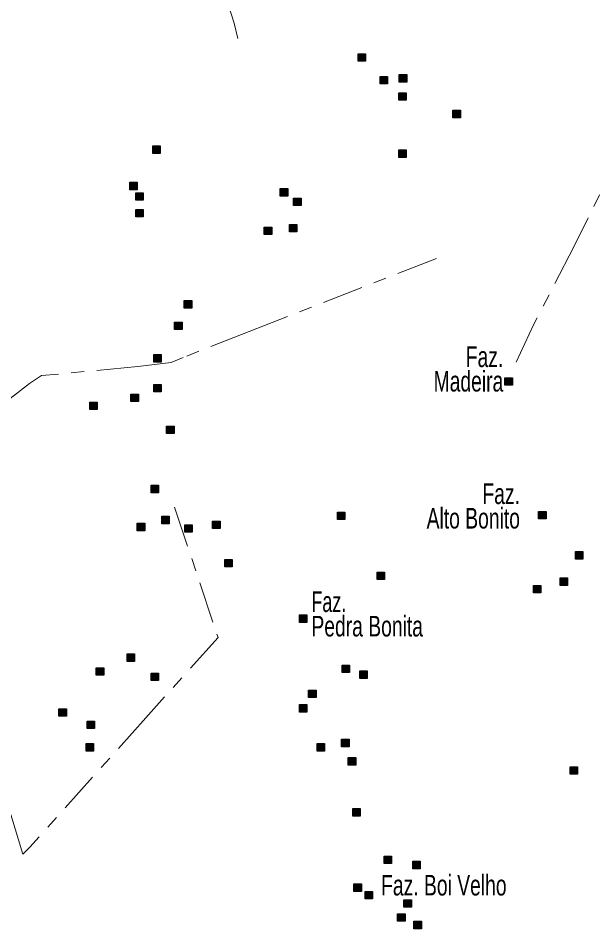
# Model space of a CAD drawing. Extents: x 445.4 to 500, y 8728.7 to 8784.
# Drawn here: x 450 to 454.47, y 8750.73 to 8757.8 of the extents above; entities that cross this region are included whole.
import ezdxf
from ezdxf.enums import TextEntityAlignment as Align

# ---------------------------------------------------------------- set-up
doc = ezdxf.new("R2010")
doc.units = 0
doc.header["$LTSCALE"] = 0.064
doc.linetypes.add('DOT_DASHED', pattern=[7.7, 5, -1.2, 0.3, -1.2])
doc.layers.add('2', color=7, linetype='Continuous', lineweight=25)
doc.layers.add('22', color=7, linetype='DOT_DASHED', lineweight=13)
doc.layers.add('61', color=7, linetype='Continuous')

msp = doc.modelspace()

# ---------------------------------------------------------------- hatches: boundary and pattern name
at = {"layer": '2'}
for points in [[(452.6438, 8757.5206), (452.7018, 8757.5206), (452.7018, 8757.4626), (452.6438, 8757.4626)], [(452.8139, 8757.3441), (452.8719, 8757.3441), (452.8719, 8757.2861), (452.8139, 8757.2861)], [(452.9632, 8757.3577), (453.0212, 8757.3577), (453.0212, 8757.2997), (452.9632, 8757.2997)], [(452.9587, 8757.2173), (453.0167, 8757.2173), (453.0167, 8757.1593), (452.9587, 8757.1593)], [(453.3795, 8757.0815), (453.4375, 8757.0815), (453.4375, 8757.0235), (453.3795, 8757.0235)], [(451.0494, 8756.8038), (451.1074, 8756.8038), (451.1074, 8756.7458), (451.0494, 8756.7458)], [(452.9582, 8756.7736), (453.0162, 8756.7736), (453.0162, 8756.7156), (452.9582, 8756.7156)], [(450.8714, 8756.522), (450.9294, 8756.522), (450.9294, 8756.464), (450.8714, 8756.464)], [(452.0392, 8756.4731), (452.0972, 8756.4731), (452.0972, 8756.4151), (452.0392, 8756.4151)], [(450.9169, 8756.4399), (450.9749, 8756.4399), (450.9749, 8756.3819), (450.9169, 8756.3819)], [(452.1427, 8756.3985), (452.2007, 8756.3985), (452.2007, 8756.3405), (452.1427, 8756.3405)], [(450.9169, 8756.3115), (450.9749, 8756.3115), (450.9749, 8756.2535), (450.9169, 8756.2535)], [(452.1096, 8756.1954), (452.1676, 8756.1954), (452.1676, 8756.1374), (452.1096, 8756.1374)], [(451.915, 8756.1747), (451.973, 8756.1747), (451.973, 8756.1167), (451.915, 8756.1167)], [(451.2938, 8755.6029), (451.3518, 8755.6029), (451.3518, 8755.5449), (451.2938, 8755.5449)], [(451.2192, 8755.4371), (451.2772, 8755.4371), (451.2772, 8755.3791), (451.2192, 8755.3791)], [(451.0577, 8755.1844), (451.1157, 8755.1844), (451.1157, 8755.1264), (451.0577, 8755.1264)], [(453.783, 8755.005), (453.841, 8755.005), (453.841, 8754.947), (453.783, 8754.947)], [(451.0577, 8754.9523), (451.1157, 8754.9523), (451.1157, 8754.8943), (451.0577, 8754.8943)], [(450.8796, 8754.8777), (450.9376, 8754.8777), (450.9376, 8754.8197), (450.8796, 8754.8197)], [(450.5608, 8754.8156), (450.6188, 8754.8156), (450.6188, 8754.7576), (450.5608, 8754.7576)], [(451.1571, 8754.6291), (451.2151, 8754.6291), (451.2151, 8754.5711), (451.1571, 8754.5711)], [(451.037, 8754.1691), (451.095, 8754.1691), (451.095, 8754.1111), (451.037, 8754.1111)], [(451.1198, 8753.9288), (451.1778, 8753.9288), (451.1778, 8753.8708), (451.1198, 8753.8708)], [(452.4823, 8753.9619), (452.5403, 8753.9619), (452.5403, 8753.9039), (452.4823, 8753.9039)], [(454.0446, 8753.9667), (454.1026, 8753.9667), (454.1026, 8753.9087), (454.0446, 8753.9087)], [(450.9293, 8753.8749), (450.9873, 8753.8749), (450.9873, 8753.8169), (450.9293, 8753.8169)], [(451.2979, 8753.8625), (451.3559, 8753.8625), (451.3559, 8753.8045), (451.2979, 8753.8045)], [(451.5133, 8753.8915), (451.5713, 8753.8915), (451.5713, 8753.8335), (451.5133, 8753.8335)], [(454.3297, 8753.6543), (454.3877, 8753.6543), (454.3877, 8753.5963), (454.3297, 8753.5963)], [(451.6085, 8753.594), (451.6665, 8753.594), (451.6665, 8753.536), (451.6085, 8753.536)], [(452.7913, 8753.4958), (452.8493, 8753.4958), (452.8493, 8753.4378), (452.7913, 8753.4378)], [(454.212, 8753.4505), (454.27, 8753.4505), (454.27, 8753.3925), (454.212, 8753.3925)], [(454.0039, 8753.3917), (454.0619, 8753.3917), (454.0619, 8753.3337), (454.0039, 8753.3337)], [(452.1883, 8753.163), (452.2463, 8753.163), (452.2463, 8753.105), (452.1883, 8753.105)], [(450.8506, 8752.8605), (450.9086, 8752.8605), (450.9086, 8752.8025), (450.8506, 8752.8025)], [(450.6104, 8752.7528), (450.6684, 8752.7528), (450.6684, 8752.6948), (450.6104, 8752.6948)], [(452.5196, 8752.7735), (452.5776, 8752.7735), (452.5776, 8752.7155), (452.5196, 8752.7155)], [(452.6563, 8752.7279), (452.7143, 8752.7279), (452.7143, 8752.6699), (452.6563, 8752.6699)], [(451.037, 8752.7113), (451.095, 8752.7113), (451.095, 8752.6533), (451.037, 8752.6533)], [(452.2587, 8752.5787), (452.3167, 8752.5787), (452.3167, 8752.5207), (452.2587, 8752.5207)], [(452.1883, 8752.4668), (452.2463, 8752.4668), (452.2463, 8752.4088), (452.1883, 8752.4088)], [(450.3206, 8752.4337), (450.3786, 8752.4337), (450.3786, 8752.3757), (450.3206, 8752.3757)], [(450.54, 8752.3384), (450.598, 8752.3384), (450.598, 8752.2804), (450.54, 8752.2804)], [(450.5318, 8752.1643), (450.5898, 8752.1643), (450.5898, 8752.1063), (450.5318, 8752.1063)], [(452.325, 8752.1643), (452.383, 8752.1643), (452.383, 8752.1063), (452.325, 8752.1063)], [(452.5155, 8752.1975), (452.5735, 8752.1975), (452.5735, 8752.1395), (452.5155, 8752.1395)], [(452.5671, 8752.055), (452.6251, 8752.055), (452.6251, 8751.997), (452.5671, 8751.997)], [(454.2889, 8751.9837), (454.3469, 8751.9837), (454.3469, 8751.9257), (454.2889, 8751.9257)], [(452.6024, 8751.6588), (452.6604, 8751.6588), (452.6604, 8751.6008), (452.6024, 8751.6008)], [(452.8456, 8751.291), (452.9036, 8751.291), (452.9036, 8751.233), (452.8456, 8751.233)], [(453.0673, 8751.2502), (453.1253, 8751.2502), (453.1253, 8751.1922), (453.0673, 8751.1922)], [(452.6107, 8751.0745), (452.6687, 8751.0745), (452.6687, 8751.0165), (452.6107, 8751.0165)], [(452.6977, 8751.0165), (452.7557, 8751.0165), (452.7557, 8750.9585), (452.6977, 8750.9585)], [(452.9994, 8750.9514), (453.0574, 8750.9514), (453.0574, 8750.8934), (452.9994, 8750.8934)], [(452.9496, 8750.8428), (453.0076, 8750.8428), (453.0076, 8750.7848), (452.9496, 8750.7848)], [(453.0763, 8750.7839), (453.1343, 8750.7839), (453.1343, 8750.7259), (453.0763, 8750.7259)]]:
    msp.add_hatch(color=256, dxfattribs=at).paths.add_polyline_path(points)

# ---------------------------------------------------------------- linework, layer by layer
for points in [[(452.6438, 8757.5206), (452.7018, 8757.5206), (452.7018, 8757.4626), (452.6438, 8757.4626)], [(452.8139, 8757.3441), (452.8719, 8757.3441), (452.8719, 8757.2861), (452.8139, 8757.2861)], [(452.9632, 8757.3577), (453.0212, 8757.3577), (453.0212, 8757.2997), (452.9632, 8757.2997)], [(452.9587, 8757.2173), (453.0167, 8757.2173), (453.0167, 8757.1593), (452.9587, 8757.1593)], [(453.3795, 8757.0815), (453.4375, 8757.0815), (453.4375, 8757.0235), (453.3795, 8757.0235)], [(451.0494, 8756.8038), (451.1074, 8756.8038), (451.1074, 8756.7458), (451.0494, 8756.7458)], [(452.9582, 8756.7736), (453.0162, 8756.7736), (453.0162, 8756.7156), (452.9582, 8756.7156)], [(450.8714, 8756.522), (450.9294, 8756.522), (450.9294, 8756.464), (450.8714, 8756.464)], [(452.0392, 8756.4731), (452.0972, 8756.4731), (452.0972, 8756.4151), (452.0392, 8756.4151)], [(450.9169, 8756.4399), (450.9749, 8756.4399), (450.9749, 8756.3819), (450.9169, 8756.3819)], [(452.1427, 8756.3985), (452.2007, 8756.3985), (452.2007, 8756.3405), (452.1427, 8756.3405)], [(450.9169, 8756.3115), (450.9749, 8756.3115), (450.9749, 8756.2535), (450.9169, 8756.2535)], [(452.1096, 8756.1954), (452.1676, 8756.1954), (452.1676, 8756.1374), (452.1096, 8756.1374)], [(451.915, 8756.1747), (451.973, 8756.1747), (451.973, 8756.1167), (451.915, 8756.1167)], [(451.2938, 8755.6029), (451.3518, 8755.6029), (451.3518, 8755.5449), (451.2938, 8755.5449)], [(451.2192, 8755.4371), (451.2772, 8755.4371), (451.2772, 8755.3791), (451.2192, 8755.3791)], [(451.0577, 8755.1844), (451.1157, 8755.1844), (451.1157, 8755.1264), (451.0577, 8755.1264)], [(453.783, 8755.005), (453.841, 8755.005), (453.841, 8754.947), (453.783, 8754.947)], [(451.0577, 8754.9523), (451.1157, 8754.9523), (451.1157, 8754.8943), (451.0577, 8754.8943)], [(450.8796, 8754.8777), (450.9376, 8754.8777), (450.9376, 8754.8197), (450.8796, 8754.8197)], [(450.5608, 8754.8156), (450.6188, 8754.8156), (450.6188, 8754.7576), (450.5608, 8754.7576)], [(451.1571, 8754.6291), (451.2151, 8754.6291), (451.2151, 8754.5711), (451.1571, 8754.5711)], [(451.037, 8754.1691), (451.095, 8754.1691), (451.095, 8754.1111), (451.037, 8754.1111)], [(451.1198, 8753.9288), (451.1778, 8753.9288), (451.1778, 8753.8708), (451.1198, 8753.8708)], [(452.4823, 8753.9619), (452.5403, 8753.9619), (452.5403, 8753.9039), (452.4823, 8753.9039)], [(454.0446, 8753.9667), (454.1026, 8753.9667), (454.1026, 8753.9087), (454.0446, 8753.9087)], [(450.9293, 8753.8749), (450.9873, 8753.8749), (450.9873, 8753.8169), (450.9293, 8753.8169)], [(451.2979, 8753.8625), (451.3559, 8753.8625), (451.3559, 8753.8045), (451.2979, 8753.8045)], [(451.5133, 8753.8915), (451.5713, 8753.8915), (451.5713, 8753.8335), (451.5133, 8753.8335)], [(454.3297, 8753.6543), (454.3877, 8753.6543), (454.3877, 8753.5963), (454.3297, 8753.5963)], [(451.6085, 8753.594), (451.6665, 8753.594), (451.6665, 8753.536), (451.6085, 8753.536)], [(452.7913, 8753.4958), (452.8493, 8753.4958), (452.8493, 8753.4378), (452.7913, 8753.4378)], [(454.212, 8753.4505), (454.27, 8753.4505), (454.27, 8753.3925), (454.212, 8753.3925)], [(454.0039, 8753.3917), (454.0619, 8753.3917), (454.0619, 8753.3337), (454.0039, 8753.3337)], [(452.1883, 8753.163), (452.2463, 8753.163), (452.2463, 8753.105), (452.1883, 8753.105)], [(450.8506, 8752.8605), (450.9086, 8752.8605), (450.9086, 8752.8025), (450.8506, 8752.8025)], [(450.6104, 8752.7528), (450.6684, 8752.7528), (450.6684, 8752.6948), (450.6104, 8752.6948)], [(452.5196, 8752.7735), (452.5776, 8752.7735), (452.5776, 8752.7155), (452.5196, 8752.7155)], [(452.6563, 8752.7279), (452.7143, 8752.7279), (452.7143, 8752.6699), (452.6563, 8752.6699)], [(451.037, 8752.7113), (451.095, 8752.7113), (451.095, 8752.6533), (451.037, 8752.6533)], [(452.2587, 8752.5787), (452.3167, 8752.5787), (452.3167, 8752.5207), (452.2587, 8752.5207)], [(452.1883, 8752.4668), (452.2463, 8752.4668), (452.2463, 8752.4088), (452.1883, 8752.4088)], [(450.3206, 8752.4337), (450.3786, 8752.4337), (450.3786, 8752.3757), (450.3206, 8752.3757)], [(450.54, 8752.3384), (450.598, 8752.3384), (450.598, 8752.2804), (450.54, 8752.2804)], [(450.5318, 8752.1643), (450.5898, 8752.1643), (450.5898, 8752.1063), (450.5318, 8752.1063)], [(452.325, 8752.1643), (452.383, 8752.1643), (452.383, 8752.1063), (452.325, 8752.1063)], [(452.5155, 8752.1975), (452.5735, 8752.1975), (452.5735, 8752.1395), (452.5155, 8752.1395)], [(452.5671, 8752.055), (452.6251, 8752.055), (452.6251, 8751.997), (452.5671, 8751.997)], [(454.2889, 8751.9837), (454.3469, 8751.9837), (454.3469, 8751.9257), (454.2889, 8751.9257)], [(452.6024, 8751.6588), (452.6604, 8751.6588), (452.6604, 8751.6008), (452.6024, 8751.6008)], [(452.8456, 8751.291), (452.9036, 8751.291), (452.9036, 8751.233), (452.8456, 8751.233)], [(453.0673, 8751.2502), (453.1253, 8751.2502), (453.1253, 8751.1922), (453.0673, 8751.1922)], [(452.6107, 8751.0745), (452.6687, 8751.0745), (452.6687, 8751.0165), (452.6107, 8751.0165)], [(452.6977, 8751.0165), (452.7557, 8751.0165), (452.7557, 8750.9585), (452.6977, 8750.9585)], [(452.9994, 8750.9514), (453.0574, 8750.9514), (453.0574, 8750.8934), (452.9994, 8750.8934)], [(452.9496, 8750.8428), (453.0076, 8750.8428), (453.0076, 8750.7848), (452.9496, 8750.7848)], [(453.0763, 8750.7839), (453.1343, 8750.7839), (453.1343, 8750.7259), (453.0763, 8750.7259)]]:
    msp.add_lwpolyline(points, close=True, dxfattribs=at)
at = {"layer": '22'}
for points in [[(451.3035, 8758.9875), (451.4201, 8758.5861), (451.6812, 8757.7583), (451.7096, 8757.6389)], [(455.254, 8757.9118), (454.3171, 8756.0218), (454.0056, 8755.4152), (453.8651, 8755.1149)], [(453.2508, 8755.9296), (451.7986, 8755.3634), (451.2846, 8755.1612), (451.1911, 8755.1223), (450.9341, 8755.0912), (450.1864, 8755.0212), (450.093, 8754.9589), (449.7269, 8754.6789), (449.5777, 8754.5766), (448.9686, 8754.1589)], [(451.2183, 8753.9994), (451.5566, 8752.9863), (450.9959, 8752.3641), (450.0963, 8751.3607), (450.0406, 8751.3064), (449.7479, 8752.2671), (449.5766, 8752.8504), (449.475, 8753.1737), (449.4067, 8753.3884)]]:
    msp.add_lwpolyline(points, dxfattribs=at)

# ---------------------------------------------------------------- texts
at = {"layer": '61', "width": 0.7}
for s, p in [('       Faz.', (453.7704, 8755.0873)), ('Madeira', (453.7704, 8754.8973)), ('          Faz.', (453.8996, 8754.0236)), ('Alto Bonito', (453.8996, 8753.8336))]:
    msp.add_text(s, height=0.16, dxfattribs=at).set_placement(p, align=Align.RIGHT)
at = {"layer": '61'}
for s, width, p in [('Faz.', 0.65, (452.2808, 8753.1855)), ('Pedra Bonita', 0.7, (452.2808, 8752.9955)), ('Faz. Boi Velho', 0.7, (452.8218, 8750.9844))]:
    msp.add_text(s, height=0.16, dxfattribs=dict(at, width=width)).set_placement(p)

doc.saveas('drawing.dxf')
